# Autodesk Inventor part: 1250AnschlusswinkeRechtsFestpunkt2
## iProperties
Category: PARTsolutions
Created: 2011-08
Part Number: 1250AnschlusswinkeRechtsFestpunkt2
Catalog Web Link: www.cadenas.de
Description: 1250 Anschlusswinkel rechts Festpunkt - Anschlusswinkel rechts Festpunkt
Document SubType Name: Modeling
Designer: PARTsolutions
Density: 1 g/cm^3
NB: 1250AnschlusswinkeRechtsFestpunkt2
NN: 1250 Anschlusswinkel rechts Festpunkt
NT: Anschlusswinkel rechts Festpunkt
NBSYN: 1250AnschlusswinkeRechtsFestpunkt2
LINA: 1250AnschlusswinkeRechtsFestpunkt2
BEST: 1250AnschlusswinkeRechtsFestpunkt
FA: 2
B: 0.000
KT: DUMMY
SUPPLIER: Kabelschlepp
ARTICLENO: 1250AnschlusswinkeRechtsFestpunkt2
BOMINFO: 1250AnschlusswinkeRechtsFestpunkt2
CREATOR: CADENAS GmbH
PSOL_IDENT_0: {\\10.0.0.251\ps_data\23d-libs\kabelschlepp\4_eketten_st\parts\1250_anschlusswinkel_rechts_f.prj},24
PSOL_IDENT_1: 3 {VTYP=3D},{NB=1250AnschlusswinkeRechtsFestpunkt2},{LINA=1250AnschlusswinkeRechtsFestpunkt2},{NN=12
PSOL_IDENT_2: 50 Anschlusswinkel rechts Festpunkt},{DATE=08.06.2007 12:30:25},{GEOMDATE=13.03.2007 11:14:00},{VERS
PSOL_IDENT_3: ION=},{LINEID=10},{LINESUBID=-1},{WBVAR=FA}  {NB=1250AnschlusswinkeRechtsFestpunkt2},{LINA=1250Ansch
PSOL_IDENT_4: lusswinkeRechtsFestpunkt2},{KT=DUMMY},{BEST=1250AnschlusswinkeRechtsFestpunkt},{FA=2},{B=0}
Title: 1250AnschlusswinkeRechtsFestpunkt2
Author: Cadenas PARTsolutions
Comments: Anschlusswinkel rechts Festpunkt
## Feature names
1. Extrusion1
2. Extrusion2
3. Extrusion3
4. Extrusion4
5. Extrusion5
6. Revolution1
7. Revolution2
8. Extrusion6
